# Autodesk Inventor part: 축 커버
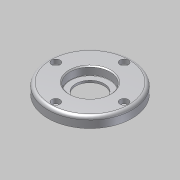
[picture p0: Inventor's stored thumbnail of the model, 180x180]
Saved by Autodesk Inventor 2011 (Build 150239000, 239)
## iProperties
Created: 2013-06
Part Number: 축 커버
Document SubType Name: Modeling
Designer: SeoGD™[esajin.kr]
Density: 1 g/cm^3
Mass: 41.026 g
Surface Area: 133.703 cm^2
Volume: 41.026 cm^3
Author: SeoGD™[esajin.kr]
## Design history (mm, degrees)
sketch "스케치1"
  geometry: C1 r 40 at (0, 0) reference; C2 r 26 at (0, 0) reference; 1 further point
  node "참조1"
  node "참조2"
extrude "돌출1" new body sketch "스케치1" distance "d0" = 10; taper "d1" = 0 deg
extrude "돌출2" join sketch "스케치1" distance "d2" = 3; taper "d3" = 0 deg
hole "구멍1" diameter "d6" = 27; stored, may be unused: countersink angle "d10" = 90 deg, drill point angle "d12" = 118 deg; dims "d4" = 10, "d5" = 10, "d7" = 6, "d8" = 38, "d9" = 8, "d11" = 8
sketch "스케치2"
  geometry: C1 r 20 at (0, 0); 1 further point
  constraints: 1 centre point, 1 coincident
  dimensions: "d13" = 40 diameter of C1
extrude "돌출3" cut sketch "스케치2" distance "d14" = 3; taper "d15" = 0 deg
sketch "스케치3"
  geometry: C1 r 1.621 at (0, 32.5) reference; 1 further point
hole "구멍2" sketch "스케치3" at (0, 32.5) diameter "d16" = 4.5; stored, may be unused: countersink angle "d20" = 90 deg, drill point angle "d22" = 118 deg; dims "d17" = 6, "d18" = 8, "d19" = 4.4, "d21" = 8
fillet "모깎기1" dims "d26" = 3, "d27" = 0.3
chamfer "모따기1" distance "d28" = 1; stored, may be unused: second distance "d29" = 2, angle "d30" = 45 deg
node "솔리드1"
pattern_circular "원형 패턴1" dims angle "d24" = 360 deg
node "참조3"
